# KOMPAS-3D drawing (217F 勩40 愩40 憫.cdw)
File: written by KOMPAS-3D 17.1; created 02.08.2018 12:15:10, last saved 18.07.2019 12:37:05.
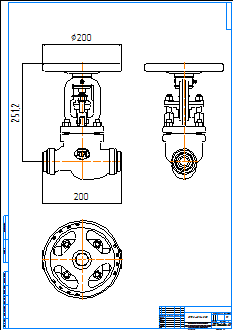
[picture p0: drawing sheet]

Sheet 1: A1, portrait

Title block, sheet 1: name: 217F Ду40 Ру40 СС; material: Внимание! Данный продукт является объектом авторского права ООО «Торговый Дом АДЛ». / Запрещается изменение, копирование, распространение / (в том числе путем копирования на другие сайты и ресурсы в Интернете) / или любое иное использование информации и объектов без предварительного / согласия правообладателя (ООО «Торговый Дом АДЛ»).; sheets: 1; organisation: ООО "Торговый дом АДЛ"; sheet format: A1; stored path: \\adlc.lan\data\АДЛ_ПКД\3D-модели\Поставщики\Zetkama\Вентили\217F\KOMPAS 2D\217F Ду40 Ру40 СС.cdw

Views: Вид 1, Проекционный вид 2, Проекционный вид 3
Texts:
  kka
  adl
Dimensions and other numbers on the sheet: 200; 251,2; 1:1; 1; 217F Ду40 Ру40 СС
